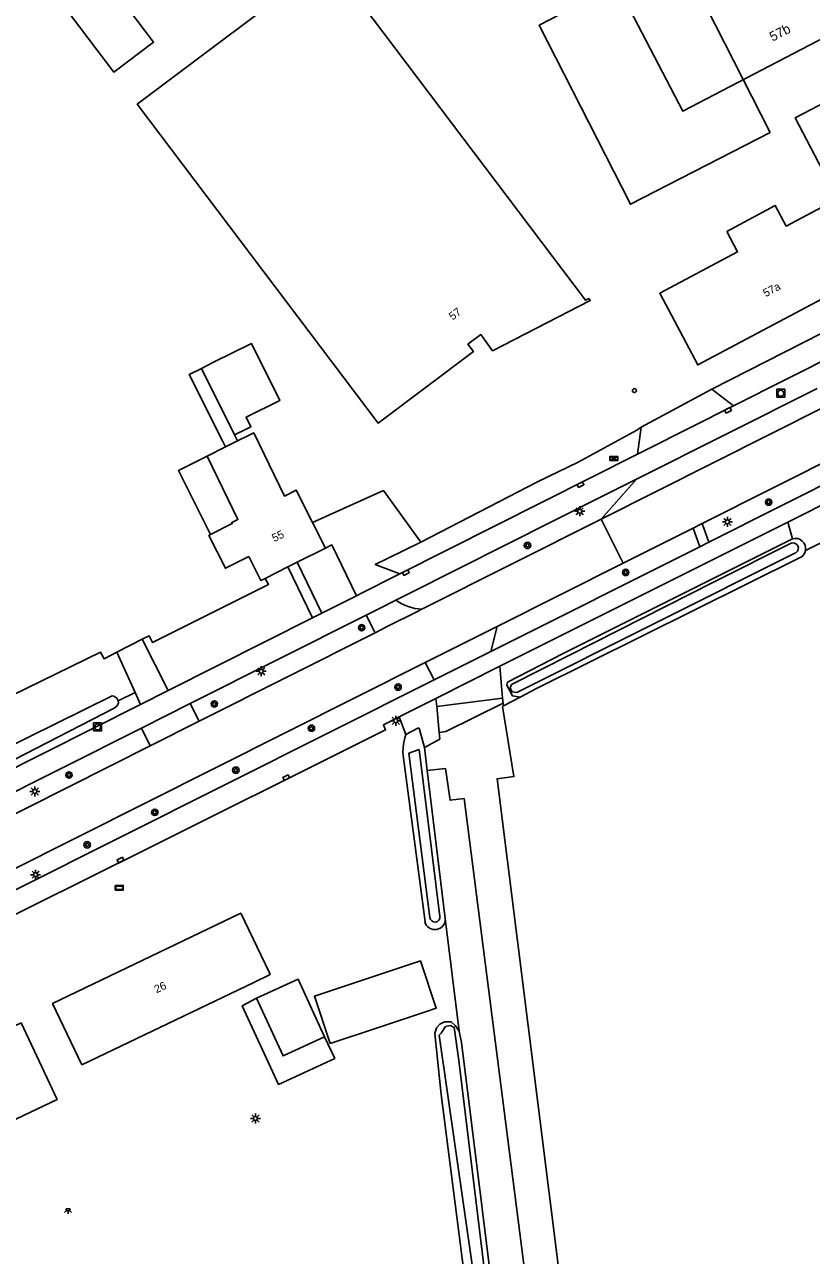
# Model space of a CAD drawing. Extents: x 140000 to 143000, y 403500 to 406000.
# Drawn here: x 141103.5 to 141201.8, y 404832.6 to 404986.4 of the extents above; entities that cross this region are included whole.
import ezdxf

# ---------------------------------------------------------------- set-up
doc = ezdxf.new("R2010")
doc.units = 0
for name, color, linetype in [('gg-afsc-erfafscheiding', 7, 'Continuous'), ('gg-afsc-hekwerk', 7, 'Continuous'), ('gg-anno-huisnummerreeks BGT', 7, 'Continuous'), ('gg-bbg-bijgebouw', 7, 'Continuous'), ('gg-bbg-hoofdgebouw', 7, 'Continuous'), ('gg-bbg-luifel en loopbrug', 7, 'Continuous'), ('gg-bbg-open loods', 7, 'Continuous'), ('gg-knt-bronhoudergrens', 7, 'Continuous'), ('gg-knt-verharding', 7, 'Continuous'), ('gg-knt-verharding nz', 7, 'Continuous'), ('gg-kntw-bovenkant insteek waterloop', 7, 'Continuous'), ('gg-kntw-waterlijn', 7, 'Continuous'), ('gt-anno-plantopografie huisnummer', 7, 'Continuous'), ('gt-bbg-plantopografie pand', 7, 'Continuous'), ('gt-grn-vlakafsluiter', 7, 'Continuous'), ('gt-grn-weggrens', 7, 'Continuous'), ('gt-symb-boom', 7, 'Continuous'), ('gt-symb-kolk', 7, 'Continuous'), ('gt-symb-lichtmast', 7, 'Continuous'), ('gt-symb-lichtpunt', 7, 'Continuous'), ('gt-symb-reclamebord', 7, 'Continuous'), ('gt-symb-rioolschacht', 7, 'Continuous'), ('gt-symb-verkeersregelinstallatiekast', 7, 'Continuous'), ('gt-symb-verkeersregelinstallatiepaal', 7, 'Continuous')]:
    doc.layers.add(name, color=color, linetype=linetype)

# ---------------------------------------------------------------- blocks, each defined once
blk = doc.blocks.new('gt0-LMAST')
at = {"layer": 'gt-symb-lichtmast'}
for p, q in [((-0.18, 0.17), (-0.45, 0.44)), ((-0.01, 0.25), (-0.01, 0.62)), ((0.17, 0.17), (0.44, 0.44)), ((-0.26, 0), (-0.63, 0)), ((-0.18, -0.18), (-0.45, -0.45)), ((-0.01, -0.25), (-0.01, -0.63)), ((0.44, -0.45), (0.17, -0.18)), ((0.24, 0), (0.62, 0))]:
    blk.add_line(p, q, dxfattribs=at)
blk.add_circle((-0.01, 0), 0.25, dxfattribs=at)
blk = doc.blocks.new('gt0-BOOM')
at = {"layer": 'gt-symb-boom'}
for radius in [0.4, 0.2]:
    blk.add_circle((0, 0), radius, dxfattribs=at)
blk = doc.blocks.new('gt0-KOLK')
at = {"layer": 'gt-symb-kolk'}
blk.add_lwpolyline([(0, 0), (0.38, 0), (0.38, 0.4), (-0.37, 0.4), (-0.37, 0), (0, 0)], dxfattribs=at)
blk = doc.blocks.new('gt0-VRIKST')
at = {"layer": 'gt-symb-verkeersregelinstallatiekast'}
for p, q in [((-0.5, -0.25), (0.5, 0.25)), ((-0.5, 0.25), (0.5, -0.25))]:
    blk.add_line(p, q, dxfattribs=at)
blk.add_lwpolyline([(0.5, 0.25), (-0.5, 0.25), (-0.5, -0.25), (0.5, -0.25)], close=True, dxfattribs=at)
blk = doc.blocks.new('gt0-VIPAAL')
at = {"layer": 'gt-symb-verkeersregelinstallatiepaal'}
blk.add_circle((0, 0), 0.25, dxfattribs=at)
blk = doc.blocks.new('gt0-RS')
at = {"layer": 'gt-symb-rioolschacht'}
blk.add_lwpolyline([(-0.5, -0.5), (0.5, -0.5), (0.5, 0.5), (-0.5, 0.5)], close=True, dxfattribs=at)
blk.add_circle((0, 0), 0.375, dxfattribs=at)
blk = doc.blocks.new('gt0-RBORD')
at = {"layer": 'gt-symb-reclamebord'}
blk.add_lwpolyline([(-0.5, 0.29), (-0.5, -0.29), (0.5, -0.29), (0.5, 0.29), (-0.5, 0.29)], dxfattribs=at)
blk.add_lwpolyline([(-0.42, -0.21), (0.42, -0.21), (0.42, 0.21), (-0.42, 0.21)], close=True, dxfattribs=at)
blk = doc.blocks.new('gt0-LPUNT')
at = {"layer": 'gt-symb-lichtpunt'}
for p, q in [((0, 0), (-0.25, 0)), ((0, 0), (0.25, 0)), ((-0.18, -0.18), (-0.44, -0.44)), ((0, -0.25), (0, -0.62)), ((0.44, -0.44), (0.18, -0.18))]:
    blk.add_line(p, q, dxfattribs=at)
blk.add_arc((0, 0), 0.25, 180, 0, dxfattribs=at)

msp = doc.modelspace()

# ---------------------------------------------------------------- linework, layer by layer
at = {"layer": 'gg-afsc-erfafscheiding'}
for p, q in [((141189.38, 404940.85), (141212.93, 404952.89)), ((141139.49, 404912.29), (141136.4, 404918.65)), ((141140.63, 404912.86), (141137.54, 404919.22)), ((141115.01, 404907.97), (141118.18, 404909.6)), ((141121.43, 404903.19), (141118.18, 404909.6)), ((141117.31, 404902.94), (141115.01, 404907.97)), ((141115.2, 404901.92), (141117.31, 404902.94)), ((141150.3, 404899.9), (141151.12, 404897.71))]:
    msp.add_line(p, q, dxfattribs=at)
for points in [[(141152.99, 404921.73), (141153.02, 404921.75), (141167.59, 404929.27), (141172.65, 404931.72), (141180.01, 404935.72), (141180.55, 404936.09)], [(141139.49, 404924.18), (141148.35, 404928.18), (141152.99, 404921.73)], [(141150.39, 404917.78), (141147.31, 404918.94), (141148.86, 404919.69), (141152.99, 404921.73)], [(141144.95, 404915.03), (141141.9, 404921.38), (141141.08, 404921)], [(141133.54, 404917.21), (141133.96, 404916.43), (141119.47, 404909.21), (141119.04, 404910.04), (141118.18, 404909.6)], [(141080.85, 404903.54), (141090.13, 404908.58), (141094.44, 404898.95), (141112.96, 404907.99), (141113.42, 404907.16), (141115.01, 404907.97)]]:
    msp.add_lwpolyline(points, dxfattribs=at)
at = {"layer": 'gg-afsc-hekwerk'}
msp.add_line((141167.59, 404929.27), (141172.65, 404931.72), dxfattribs=at)
at = {"layer": 'gg-bbg-bijgebouw'}
msp.add_line((141125.59, 404943.46), (141129.73, 404935.15), dxfattribs=at)
for points in [[(141196.68, 404972.94), (141185.27, 404995.41), (141167.78, 404986.35), (141179.2, 404963.97), (141196.68, 404972.94)], [(141209.98, 404969.46), (141205.6, 404977.81), (141199.78, 404974.76), (141204.16, 404966.41), (141209.98, 404969.46)], [(141129.73, 404935.15), (141131.16, 404935.86), (141131.77, 404936.16), (141131.18, 404937.34), (141135.38, 404939.43), (141131.83, 404946.57), (141127.03, 404944.18), (141125.59, 404943.46)], [(141141.69, 404859.06), (141139.71, 404864.97), (141152.96, 404869.4), (141154.94, 404863.49), (141153.71, 404863.08), (141147.47, 404861), (141141.69, 404859.06)], [(141132.46, 404864.72), (141137.67, 404867.12), (141140.99, 404859.92)], [(141132.46, 404864.72), (141135.79, 404857.52), (141140.99, 404859.92)], [(141091.99, 404844.71), (141091.25, 404846.29), (141089.23, 404855.13), (141103.05, 404861.65), (141107.56, 404852.06), (141100.71, 404848.82)]]:
    msp.add_lwpolyline(points, dxfattribs=at)
at = {"layer": 'gg-bbg-hoofdgebouw'}
for p, q in [((141130.1, 404934.4), (141128.58, 404933.64)), ((141128.58, 404933.64), (141126.29, 404932.49)), ((141141.08, 404921), (141139.49, 404924.18)), ((141137.54, 404919.22), (141141.08, 404921)), ((141133.54, 404917.21), (141136.4, 404918.65)), ((141137.54, 404919.22), (141136.4, 404918.65))]:
    msp.add_line(p, q, dxfattribs=at)
for points in [[(141174.02, 404952.2), (141173.58, 404951.96), (141141.51, 404994.46), (141117.57, 404976.47), (141147.66, 404936.62), (141159.59, 404945.56), (141158.9, 404946.48), (141160.5, 404947.68), (141161.97, 404945.65), (141174.17, 404951.92), (141174.02, 404952.2)], [(141191.23, 404960.58), (141192.59, 404958.01), (141182.86, 404952.85), (141187.61, 404943.88), (141209.92, 404955.71), (141205.17, 404964.68), (141198.67, 404961.23), (141197.3, 404963.8), (141191.23, 404960.58)], [(141139.49, 404924.18), (141137.45, 404928.24), (141135.97, 404927.5), (141132.12, 404935.41), (141131.54, 404935.12), (141130.1, 404934.4)], [(141126.29, 404932.49), (141130.14, 404924.57), (141129.38, 404924.19), (141129.45, 404924.05), (141126.73, 404922.68)], [(141126.73, 404922.68), (141126.53, 404922.58), (141128.58, 404918.47), (141131.51, 404919.94), (141133.01, 404916.95), (141133.54, 404917.21)], [(141132.12, 404866.71), (141134.17, 404867.7), (141134.08, 404867.89), (141130.5, 404875.36), (141106.98, 404864.09), (141110.66, 404856.42), (141132.12, 404866.71)]]:
    msp.add_lwpolyline(points, dxfattribs=at)
at = {"layer": 'gg-bbg-luifel en loopbrug'}
msp.add_line((141129.73, 404935.15), (141130.1, 404934.4), dxfattribs=at)
for points in [[(141125.59, 404943.46), (141124.07, 404942.71), (141128.21, 404934.39), (141128.58, 404933.64)], [(141126.29, 404932.49), (141122.72, 404930.69), (141126.73, 404922.68)], [(141132.46, 404864.72), (141130.7, 404863.79), (141135.24, 404853.95), (141142.25, 404857.2), (141140.99, 404859.92)]]:
    msp.add_lwpolyline(points, dxfattribs=at)
at = {"layer": 'gg-bbg-open loods'}
msp.add_lwpolyline([(141103.98, 404994.6), (141114.66, 404980.47), (141119.61, 404984.21), (141108.93, 404998.34)], dxfattribs=at)
at = {"layer": 'gg-knt-bronhoudergrens'}
for p, q in [((141165.42, 404902.37), (141163.34, 404901.27)), ((141163.34, 404901.27), (141163.22, 404901.21)), ((141155.4, 404897.1), (141153.46, 404896.07))]:
    msp.add_line(p, q, dxfattribs=at)
for points in [[(141170.12, 404751.25), (141173.95, 404752.39), (141173.87, 404752.76), (141179.74, 404753.43), (141176.7, 404779.3), (141162.54, 404892.17), (141164.65, 404892.44), (141163.22, 404901.21)], [(141051.07, 404724.16), (141167.7, 404759), (141168.3, 404759.18), (141169.64, 404759.58), (141170.36, 404759.8), (141171.64, 404760.2), (141171.43, 404762.11), (141172.65, 404762.53), (141171.91, 404768.56), (141173.87, 404768.99), (141158.42, 404889.69), (141156.67, 404889.48), (141156.09, 404893.45), (141153.81, 404893.2)]]:
    msp.add_lwpolyline(points, dxfattribs=at)
at = {"layer": 'gg-knt-verharding'}
for p, q in [((141214.55, 404950.1), (141192.09, 404938.79)), ((141202.53, 404940.94), (141179.95, 404929.59)), ((141192.09, 404938.79), (141189.38, 404940.85)), ((141203.63, 404938.75), (141175.54, 404924.62)), ((141180.1, 404932.74), (141180.55, 404936.09)), ((141180.1, 404932.74), (141150.39, 404917.78)), ((141179.95, 404929.59), (141175.54, 404924.62)), ((141198.89, 404924.25), (141206.41, 404928.02)), ((141175.54, 404924.62), (141153.14, 404913.35)), ((141162.9, 404906.22), (141198.89, 404924.25)), ((141178.31, 404919.11), (141187.03, 404923.49)), ((141187.03, 404923.49), (141188.18, 404924.07)), ((141187.86, 404921.16), (141187.03, 404923.49)), ((141189.02, 404921.74), (141188.18, 404924.07)), ((141198.89, 404924.25), (141199.46, 404922.15)), ((141189.02, 404921.74), (141187.86, 404921.16)), ((141187.86, 404921.16), (141161.77, 404908.08)), ((141178.31, 404919.11), (141162.54, 404911.18)), ((141144.95, 404915.03), (141140.63, 404912.86)), ((141139.49, 404912.29), (141121.43, 404903.19)), ((141124.18, 404901.57), (141146.17, 404912.62)), ((141140.63, 404912.86), (141139.49, 404912.29)), ((141146.17, 404912.62), (141147.29, 404910.41)), ((141162.54, 404911.18), (141153.57, 404906.68)), ((141162.54, 404911.18), (141161.77, 404908.08)), ((141147.29, 404910.41), (141125.3, 404899.34)), ((141161.77, 404908.08), (141154.67, 404904.51)), ((141153.57, 404906.68), (141101.3, 404880.43)), ((141154.67, 404904.51), (141153.57, 404906.68)), ((141154.89, 404902.2), (141162.9, 404906.22)), ((141163.21, 404902.24), (141162.9, 404906.22)), ((141154.67, 404904.51), (141102.37, 404878.28)), ((141121.43, 404903.19), (141117.99, 404901.45)), ((141117.99, 404901.45), (141095.89, 404890.32)), ((141118.08, 404898.5), (141124.18, 404901.57)), ((141124.18, 404901.57), (141125.3, 404899.34)), ((141150.3, 404899.9), (141154.89, 404902.2)), ((141154.89, 404902.2), (141155, 404901.18)), ((141155, 404901.18), (141163.21, 404902.24)), ((141163.21, 404902.24), (141163.29, 404901.6)), ((141163.29, 404901.6), (141163.34, 404901.27)), ((141155, 404901.18), (141155.32, 404897.96)), ((141118.08, 404898.5), (141119.2, 404896.28)), ((141155.32, 404897.96), (141155.4, 404897.1)), ((141157.78, 404860.62), (141156.05, 404874.7))]:
    msp.add_line(p, q, dxfattribs=at)
for points in [[(141188.18, 404924.07), (141232.61, 404946.38), (141246.73, 404953.38)], [(141247.78, 404951.3), (141206.76, 404930.64), (141189.02, 404921.74)], [(141180.55, 404936.09), (141182.17, 404937), (141189.38, 404940.85)], [(141192.09, 404938.79), (141181.15, 404933.27), (141180.1, 404932.74)], [(141179.95, 404929.59), (141175.8, 404927.51), (141151.46, 404915.27), (141149.87, 404914.47)], [(141150.39, 404917.78), (141149.9, 404917.53), (141145.78, 404915.45), (141144.95, 404915.03)], [(141146.17, 404912.62), (141147.83, 404913.45), (141149.87, 404914.47)], [(141150.3, 404899.9), (141148.34, 404898.92), (141148.61, 404898.29), (141115.54, 404881.79), (141114.68, 404881.36), (141101.25, 404874.66), (141097.77, 404872.93), (141097.3, 404872.69), (141097.1, 404873.17), (141095.65, 404872.44), (141088.72, 404868.96)], [(141053.07, 404865.75), (141068.93, 404873.8), (141118.08, 404898.5)], [(141119.2, 404896.28), (141083.44, 404878.28), (141069.94, 404871.67), (141063.22, 404866.6)]]:
    msp.add_lwpolyline(points, dxfattribs=at)
msp.add_arc((141153.52, 404919.78), 6.44, 235.4692, 266.6877, dxfattribs=at)
at = {"layer": 'gg-knt-verharding nz'}
msp.add_line((141125.3, 404899.34), (141119.2, 404896.28), dxfattribs=at)
msp.add_lwpolyline([(141153.14, 404913.35), (141152.52, 404913.04), (141148.9, 404911.22), (141147.29, 404910.41)], dxfattribs=at)
at = {"layer": 'gg-kntw-bovenkant insteek waterloop'}
for p, q in [((141151.12, 404897.71), (141152.64, 404898.48)), ((141153.81, 404893.2), (141153.46, 404896.07)), ((141153.53, 404874.26), (141150.8, 404895.08)), ((141153.81, 404893.2), (141156.05, 404874.7))]:
    msp.add_line(p, q, dxfattribs=at)
for points in [[(141163.84, 404904.23), (141170.81, 404907.81), (141199.46, 404922.15)], [(141200.4, 404919.8), (141167.48, 404903.46), (141165.42, 404902.37)], [(141165.42, 404902.37), (141164.46, 404902.54), (141163.74, 404903.86), (141163.84, 404904.23)], [(141115.2, 404901.92), (141115.03, 404902.24), (141114.63, 404902.49), (141114.43, 404902.54), (141100.42, 404895.59), (141099.43, 404895), (141098.87, 404894.47), (141098.72, 404894.13), (141098.81, 404893.59), (141098.93, 404893.39)], [(141115.2, 404901.92), (141115.22, 404901.61), (141115.02, 404901.25), (141114.68, 404900.98), (141099.36, 404893.12), (141099.08, 404893.14), (141098.93, 404893.39)], [(141153.46, 404896.07), (141152.79, 404898.47), (141152.64, 404898.48)], [(141150.8, 404895.08), (141150.74, 404895.54), (141150.84, 404896.48), (141150.99, 404897.26), (141151.12, 404897.71)], [(141157.78, 404860.62), (141157.28, 404861.32), (141156.8, 404861.79), (141155.97, 404861.76), (141155.4, 404861.49), (141154.95, 404861.03), (141154.75, 404860.33), (141155.56, 404852.68), (141161.42, 404806.82), (141162.18, 404800), (141164.58, 404782.88), (141167.37, 404761.49)], [(141157.78, 404860.62), (141158.07, 404859.19), (141160.67, 404838.43), (141165.57, 404798.74), (141168.37, 404777.38), (141170.27, 404760.63), (141169.53, 404760.53)]]:
    msp.add_lwpolyline(points, dxfattribs=at)
for centre, radius, start, end in [((141199.83, 404920.93), 1.27, 349.5327, 106.9593), ((141199.83, 404920.93), 1.27, 296.7432, 349.5778), ((141154.77, 404874.59), 1.29, 194.9635, 4.5344)]:
    msp.add_arc(centre, radius, start, end, dxfattribs=at)
at = {"layer": 'gg-kntw-waterlijn'}
for p, q in [((141199.85, 404920.42), (141165.01, 404902.93)), ((141152.78, 404895.82), (141151.5, 404895.34)), ((141154.14, 404874.81), (141151.5, 404895.34)), ((141155.4, 404874.94), (141152.78, 404895.82))]:
    msp.add_line(p, q, dxfattribs=at)
for points in [[(141164.33, 404903.95), (141171.69, 404907.63), (141189.65, 404916.76), (141199.3, 404921.61)], [(141164.33, 404903.95), (141164.16, 404903.51), (141164.43, 404903.01), (141165.01, 404902.93)], [(141169.53, 404760.53), (141167.71, 404775.73), (141166.35, 404787.6), (141164.54, 404799.85), (141163.61, 404806.48), (141162.17, 404818.59), (141161.14, 404829.3), (141157.75, 404856.93), (141157.16, 404861.07), (141156.73, 404861.34), (141156.1, 404861.21), (141155.53, 404860.38), (141155.31, 404860.11), (141159.46, 404831.12), (141162.15, 404807.23), (141162.92, 404800.47), (141164.75, 404787.98), (141166.58, 404772.52), (141168.06, 404761.04), (141168.15, 404760.34)]]:
    msp.add_lwpolyline(points, dxfattribs=at)
for centre, radius, start, end in [((141199.53, 404920.99), 0.661, 38.9283, 110.4444), ((141199.53, 404920.99), 0.659, 299.2435, 38.7619), ((141154.77, 404874.88), 0.63, 185.9237, 5.4613)]:
    msp.add_arc(centre, radius, start, end, dxfattribs=at)
at = {"layer": 'gt-bbg-plantopografie pand'}
msp.add_lwpolyline([(141173.84, 405063.49), (141212.37, 404989.48), (141185.75, 404975.62), (141162.93, 405019.44), (141161.47, 405018.68), (141155.12, 405030.88), (141153.93, 405030.26), (141150.87, 405036.14), (141152.15, 405036.8), (141149.03, 405042.8), (141150.45, 405043.54), (141147.27, 405049.66), (141173.84, 405063.49)], dxfattribs=at)
at = {"layer": 'gt-grn-vlakafsluiter'}
for points in [[(141210.4, 404925.29), (141207.65, 404923.96), (141201.08, 404920.7)], [(141163.29, 404901.6), (141156.15, 404898.05), (141155.32, 404897.96)]]:
    msp.add_lwpolyline(points, dxfattribs=at)
at = {"layer": 'gt-grn-weggrens'}
for p, q in [((141175.54, 404924.62), (141178.31, 404919.11)), ((141117.99, 404901.45), (141117.31, 404902.94))]:
    msp.add_line(p, q, dxfattribs=at)

# ---------------------------------------------------------------- block references
at = {"layer": 'gt-symb-boom'}
for p in [(141196.48, 404926.74), (141166.34, 404921.33), (141178.61, 404917.95), (141145.62, 404911.04), (141150.17, 404903.62), (141127.2, 404901.51), (141139.34, 404898.47), (141109.04, 404892.63), (141129.89, 404893.23), (141119.76, 404887.96), (141111.31, 404883.9)]:
    msp.add_blockref('gt0-BOOM', p, dxfattribs=at)
at = {"layer": 'gt-symb-kolk'}
for p, rotation in [((141191.31, 404938.39), -153.2653284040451), ((141172.88, 404929.11), -153.2653284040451), ((141151.06, 404918.11), -153.2653284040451), ((141136.26, 404892.13), 26.518134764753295), ((141115.56, 404881.82), 26.51813476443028)]:
    msp.add_blockref('gt0-KOLK', p, dxfattribs=dict(at, rotation=rotation))
at = {"layer": 'gt-symb-lichtmast'}
for p in [(141172.87, 404925.6), (141191.33, 404924.27), (141133.07, 404905.6), (141149.89, 404899.41), (141104.78, 404890.58), (141104.87, 404880.17), (141132.35, 404849.7)]:
    msp.add_blockref('gt0-LMAST', p, dxfattribs=at)
at = {"layer": 'gt-symb-lichtpunt'}
msp.add_blockref('gt0-LPUNT', (141108.92, 404838.39), dxfattribs=at)
at = {"layer": 'gt-symb-reclamebord'}
msp.add_blockref('gt0-RBORD', (141115.33, 404878.53), dxfattribs=at)
at = {"layer": 'gt-symb-rioolschacht'}
for p in [(141197.98, 404940.34), (141112.62, 404898.64)]:
    msp.add_blockref('gt0-RS', p, dxfattribs=at)
at = {"layer": 'gt-symb-verkeersregelinstallatiekast'}
msp.add_blockref('gt0-VRIKST', (141177.13, 404932.2), dxfattribs=at)
at = {"layer": 'gt-symb-verkeersregelinstallatiepaal'}
msp.add_blockref('gt0-VIPAAL', (141179.7, 404940.68), dxfattribs=at)

# ---------------------------------------------------------------- texts
at = {"layer": 'gg-anno-huisnummerreeks BGT'}
for s, rotation, p in [('57a', 27.9, (141196.1, 404952.34)), ('57', 36.9, (141156.98, 404949.42)), ('55', 26.6, (141134.71, 404921.72)), ('26', 25.6, (141119.98, 404865.33))]:
    msp.add_text(s, height=1, rotation=rotation, dxfattribs=at).set_placement(p)
at = {"layer": 'gt-anno-plantopografie huisnummer'}
msp.add_text('57b', height=1.2, rotation=27.4962, dxfattribs=at).set_placement((141196.97, 404984.28))

doc.saveas('drawing.dxf')
